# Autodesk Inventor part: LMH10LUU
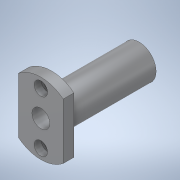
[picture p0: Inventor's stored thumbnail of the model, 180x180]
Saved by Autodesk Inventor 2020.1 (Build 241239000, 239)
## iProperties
Created: 2020-04
Part Number: LMH10LUU
Material: Standard
Document SubType Name: Modeling
Designer: Safarabadi
Density: 1 g/cm^3
Appearance: Default
Author: Safarabadi
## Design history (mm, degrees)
derived "LMH10LUU.ipt"
feature "Solid1::LMH10LUU.ipt" dims "d0" = 10
tag "TaggingFeature1"
body "Solid1"
